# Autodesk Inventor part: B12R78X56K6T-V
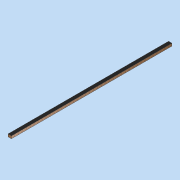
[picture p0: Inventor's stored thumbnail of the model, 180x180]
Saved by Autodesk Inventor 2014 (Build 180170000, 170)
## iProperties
Created: 2011-08
Part Number: B12R78X56K6T-V
Document SubType Name: Modeling
Designer: david.appleford
Density: 0.437859 g/cm^3
Description: Roof Edge Beam 3w - 6 Locks
Mass: 7000 g
Surface Area: 9896.16 cm^2
Volume: 15986.9 cm^3
Cost Center: £40.00
Material: 000 Redwood
Appearance: Wood (Oak)
Justset: False
Title: Roof Edge Beam 3w - 6 Locks
Author: david.appleford
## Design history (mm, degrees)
sketch "Sketch1"
  geometry: L1 (39, -34)-(-39, -34); L2 (-39, -34)-(-39, 3626); L3 (-39, 3626)-(39, 3626); L4 (39, 3626)-(39, -34); 1 further point
  constraints: 8 end point, 2 parallel, 1 horizontal, 1 perpendicular, 1 other
  dimensions: "d2" = 78 distance between parallel lines of L2 L4; "d3" = 34 distance from line of point (0, 0) L1; "d4" = 39 distance from line of point (0, 0) L2 (= 0.5 x d2); "d5" = 3660 distance of L3.end L1.start
extrude "Extrusion1" new body sketch "Sketch1" distance "d0" = 56; taper "d1" = 0 deg
body "Solid1"
